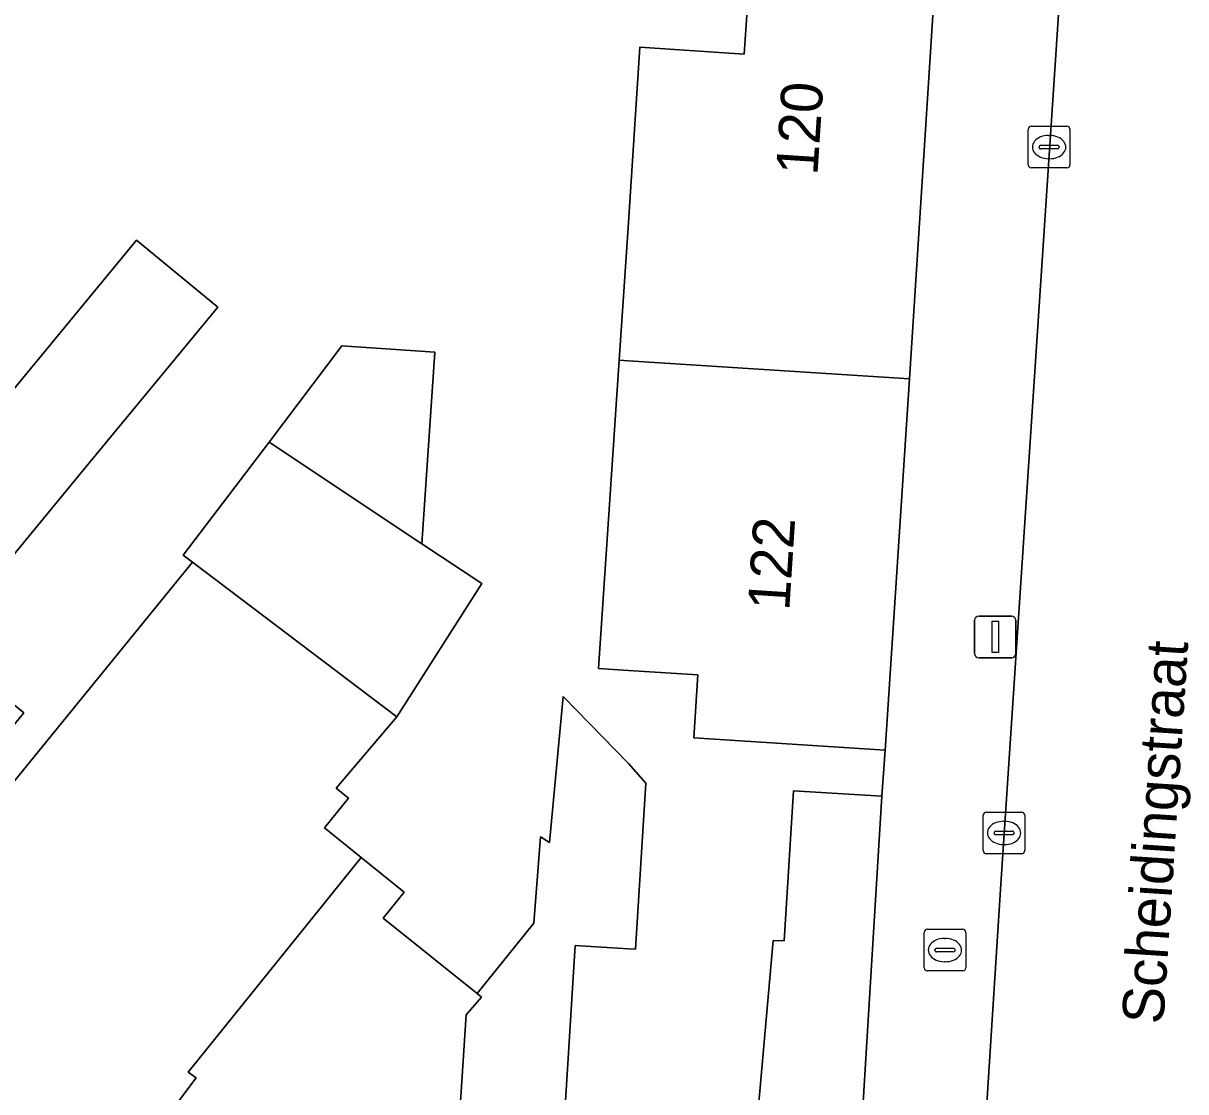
# Model space of a CAD drawing. Extents: x 160157 to 160921, y 381516 to 382045.
# Drawn here: x 160485.46 to 160513.39, y 381831.28 to 381856.97 of the extents above; entities that cross this region are included whole.
import ezdxf

# ---------------------------------------------------------------- set-up
doc = ezdxf.new("R2010")
doc.units = 0
for name, color, linetype in [('IMGEO_Brandkraan', 7, 'Continuous'), ('IMGEO_Erf', 7, 'Continuous'), ('IMGEO_Kolk', 7, 'Continuous'), ('IMGEO_Lichtmast', 7, 'Continuous'), ('IMGEO_Openbare_ruimte_label', 7, 'Continuous'), ('IMGEO_Pand', 7, 'Continuous'), ('IMGEO_Pand_nummerreeks', 7, 'Continuous'), ('IMGEO_Rijbaan_lokaal_open', 7, 'Continuous'), ('IMGEO_Voetpad_open', 7, 'Continuous')]:
    doc.layers.add(name, color=color, linetype=linetype)

msp = doc.modelspace()

# ---------------------------------------------------------------- linework, layer by layer
at = {"layer": 'IMGEO_Brandkraan'}
for p, q in [((160507.106, 381834.263), (160507.106, 381835.115)), ((160507.181, 381835.189), (160508.033, 381835.189)), ((160507.594, 381834.969), (160507.619, 381834.969)), ((160508.107, 381835.115), (160508.107, 381834.263)), ((160507.365, 381834.683), (160507.365, 381834.695)), ((160507.408, 381834.732), (160507.806, 381834.732)), ((160507.849, 381834.695), (160507.849, 381834.683)), ((160507.803, 381834.646), (160507.405, 381834.646)), ((160507.617, 381834.409), (160507.592, 381834.409)), ((160508.033, 381834.189), (160507.181, 381834.189))]:
    msp.add_line(p, q, dxfattribs=at)
for points in [[(160507.106, 381834.263), (160507.106, 381835.115)], [(160507.181, 381835.189), (160508.033, 381835.189)], [(160508.107, 381835.115), (160508.107, 381834.263)], [(160508.033, 381834.189), (160507.181, 381834.189)]]:
    msp.add_lwpolyline(points, dxfattribs=at)
for centre, radius, start, end in [((160507.183, 381835.113), 0.0765, 91.552, 178.448), ((160507.183, 381835.113), 0.0765, 91.552, 178.448), ((160508.031, 381835.113), 0.0765, 1.552, 88.448), ((160508.031, 381835.113), 0.0765, 1.552, 88.448), ((160507.405, 381834.692), 0.0403, 85.8775, 175.7526), ((160507.81, 381834.694), 0.0386, 1.7309, 96.639), ((160507.402, 381834.682), 0.0366, 178.938, 274.7102), ((160507.806, 381834.689), 0.043, 264.8664, 352.4533), ((160507.183, 381834.265), 0.0765, 181.552, 268.448), ((160507.183, 381834.265), 0.0765, 181.552, 268.448), ((160508.031, 381834.265), 0.0765, 271.552, 358.448), ((160508.031, 381834.265), 0.0765, 271.552, 358.448)]:
    msp.add_arc(centre, radius, start, end, dxfattribs=at)
for centre, major_axis, ratio, start_param, end_param in [((160507.593, 381834.689), (-0.387, 0.002), 0.722429, 4.712389, 7.853982), ((160507.618, 381834.689), (-0.39, 0.002), 0.717154, 1.570796, 4.712389)]:
    msp.add_ellipse(centre, major_axis=major_axis, ratio=ratio, start_param=start_param, end_param=end_param, dxfattribs=at)
at = {"layer": 'IMGEO_Erf'}
for points in [[(160503.001, 381829.486), (160503.479, 381834.92), (160503.742, 381834.909), (160503.965, 381838.518), (160506.091, 381838.386), (160506.173, 381839.496), (160501.57, 381839.794), (160501.668, 381841.304), (160500.001, 381841.412), (160499.283, 381841.461), (160499.779, 381848.873), (160500, 381852.181), (160500.273, 381856.394), (160502.782, 381856.231), (160502.874, 381857.649)], [(160484.957, 381847.845), (160488.178, 381851.756), (160490.129, 381850.149), (160486.907, 381846.238), (160483.459, 381842.052), (160485.473, 381840.393), (160483.484, 381837.978)], [(160483.249, 381836.314), (160489.523, 381844.017), (160489.303, 381844.183), (160491.363, 381846.903), (160493.113, 381849.214), (160495.348, 381849.064), (160495.039, 381844.456), (160496.477, 381843.499), (160494.435, 381840.297), (160492.975, 381838.584), (160493.273, 381838.344), (160492.694, 381837.625), (160493.577, 381836.913), (160494.608, 381836.082), (160494.108, 381835.46), (160496.361, 381833.644), (160497.725, 381835.337), (160497.884, 381837.409), (160498.102, 381837.278), (160498.428, 381840.783), (160500, 381839.172), (160500.415, 381838.702), (160500.169, 381834.713), (160500, 381834.723), (160498.719, 381834.802), (160498.409, 381829.769)]]:
    msp.add_lwpolyline(points, dxfattribs=at)
at = {"layer": 'IMGEO_Kolk'}
for p, q in [((160509.609, 381853.568), (160509.609, 381854.42)), ((160509.684, 381854.494), (160510.536, 381854.494)), ((160510.097, 381854.274), (160510.122, 381854.274)), ((160510.61, 381854.42), (160510.61, 381853.568)), ((160509.868, 381853.988), (160509.868, 381854)), ((160509.911, 381854.037), (160510.309, 381854.037)), ((160510.352, 381854), (160510.352, 381853.988)), ((160510.306, 381853.951), (160509.908, 381853.951)), ((160510.12, 381853.714), (160510.095, 381853.714)), ((160510.536, 381853.494), (160509.684, 381853.494)), ((160508.527, 381837.08), (160508.527, 381837.932)), ((160508.602, 381838.006), (160509.454, 381838.006)), ((160509.015, 381837.786), (160509.04, 381837.786)), ((160509.528, 381837.932), (160509.528, 381837.08)), ((160508.786, 381837.5), (160508.786, 381837.512)), ((160508.829, 381837.549), (160509.227, 381837.549)), ((160509.27, 381837.512), (160509.27, 381837.5)), ((160509.224, 381837.463), (160508.826, 381837.463)), ((160509.038, 381837.226), (160509.013, 381837.226)), ((160509.454, 381837.006), (160508.602, 381837.006))]:
    msp.add_line(p, q, dxfattribs=at)
for points in [[(160509.609, 381853.568), (160509.609, 381854.42)], [(160509.684, 381854.494), (160510.536, 381854.494)], [(160510.61, 381854.42), (160510.61, 381853.568)], [(160510.536, 381853.494), (160509.684, 381853.494)], [(160508.527, 381837.08), (160508.527, 381837.932)], [(160508.602, 381838.006), (160509.454, 381838.006)], [(160509.528, 381837.932), (160509.528, 381837.08)], [(160509.454, 381837.006), (160508.602, 381837.006)]]:
    msp.add_lwpolyline(points, dxfattribs=at)
for centre, radius, start, end in [((160509.686, 381854.418), 0.0765, 91.552, 178.448), ((160509.686, 381854.418), 0.0765, 91.552, 178.448), ((160510.534, 381854.418), 0.0765, 1.552, 88.448), ((160510.534, 381854.418), 0.0765, 1.552, 88.448), ((160509.908, 381853.997), 0.0403, 85.8775, 175.7526), ((160509.905, 381853.987), 0.0366, 178.938, 274.7102), ((160510.309, 381853.994), 0.043, 264.8664, 352.4533), ((160510.313, 381853.999), 0.0386, 1.7309, 96.639), ((160509.686, 381853.57), 0.0765, 181.552, 268.448), ((160509.686, 381853.57), 0.0765, 181.552, 268.448), ((160510.534, 381853.57), 0.0765, 271.552, 358.448), ((160510.534, 381853.57), 0.0765, 271.552, 358.448), ((160508.604, 381837.93), 0.0765, 91.552, 178.448), ((160508.604, 381837.93), 0.0765, 91.552, 178.448), ((160509.452, 381837.93), 0.0765, 1.552, 88.448), ((160509.452, 381837.93), 0.0765, 1.552, 88.448), ((160508.826, 381837.509), 0.0403, 85.8775, 175.7526), ((160508.823, 381837.499), 0.0366, 178.938, 274.7102), ((160509.227, 381837.506), 0.043, 264.8664, 352.4533), ((160509.231, 381837.511), 0.0386, 1.7309, 96.639), ((160508.604, 381837.082), 0.0765, 181.552, 268.448), ((160508.604, 381837.082), 0.0765, 181.552, 268.448), ((160509.452, 381837.082), 0.0765, 271.552, 358.448), ((160509.452, 381837.082), 0.0765, 271.552, 358.448)]:
    msp.add_arc(centre, radius, start, end, dxfattribs=at)
for centre, major_axis, ratio, start_param, end_param in [((160510.096, 381853.994), (-0.387, 0.002), 0.722429, 4.712389, 7.853982), ((160510.121, 381853.994), (-0.39, 0.002), 0.717154, 1.570796, 4.712389), ((160509.014, 381837.506), (-0.387, 0.002), 0.722429, 4.712389, 7.853982), ((160509.039, 381837.506), (-0.39, 0.002), 0.717154, 1.570796, 4.712389)]:
    msp.add_ellipse(centre, major_axis=major_axis, ratio=ratio, start_param=start_param, end_param=end_param, dxfattribs=at)
at = {"layer": 'IMGEO_Lichtmast'}
for p, q in [((160508.32, 381841.818), (160508.32, 381842.618)), ((160508.32, 381842.618), (160508.32, 381841.818)), ((160508.42, 381842.718), (160509.21, 381842.718)), ((160509.21, 381842.718), (160508.42, 381842.718)), ((160509.31, 381842.618), (160509.31, 381841.818)), ((160509.31, 381841.818), (160509.31, 381842.618)), ((160509.21, 381841.718), (160508.42, 381841.718)), ((160508.42, 381841.718), (160509.21, 381841.718))]:
    msp.add_line(p, q, dxfattribs=at)
msp.add_lwpolyline([(160508.74, 381842.593), (160508.89, 381842.593), (160508.89, 381841.843), (160508.74, 381841.843), (160508.74, 381842.593)], dxfattribs=at)
for centre, start, end in [((160508.42, 381842.618), 90, 180), ((160508.42, 381842.618), 90, 180), ((160509.21, 381842.618), 0, 90), ((160509.21, 381842.618), 360, 90), ((160508.42, 381841.818), 180, 270), ((160508.42, 381841.818), 180, 270), ((160509.21, 381841.818), 270, 0), ((160509.21, 381841.818), 270, 0)]:
    msp.add_arc(centre, 0.1, start, end, dxfattribs=at)
at = {"layer": 'IMGEO_Pand'}
for points in [[(160506.751, 381848.424), (160507.527, 381860.411), (160502.175, 381861.609), (160500.129, 381858.808), (160502.874, 381857.649), (160502.782, 381856.231), (160500.273, 381856.394), (160500, 381852.181), (160499.779, 381848.873), (160500, 381848.859)], [(160483.459, 381842.052), (160486.907, 381846.238), (160490.129, 381850.149), (160488.178, 381851.756), (160484.957, 381847.845), (160476.341, 381837.384), (160480.304, 381834.119), (160483.484, 381837.978), (160485.473, 381840.393)], [(160491.363, 381846.903), (160495.039, 381844.456), (160495.348, 381849.064), (160493.113, 381849.214)], [(160506.751, 381848.424), (160500, 381848.859), (160499.779, 381848.873), (160499.283, 381841.461), (160500.001, 381841.412), (160501.668, 381841.304), (160501.57, 381839.794), (160506.173, 381839.496)], [(160495.039, 381844.456), (160491.363, 381846.903), (160489.303, 381844.183), (160489.523, 381844.017), (160494.435, 381840.297), (160496.477, 381843.499)], [(160489.609, 381831.618), (160489.422, 381831.756), (160493.577, 381836.913), (160492.694, 381837.625), (160493.273, 381838.344), (160492.975, 381838.584), (160494.435, 381840.297), (160489.523, 381844.017), (160483.249, 381836.314), (160481.128, 381833.441), (160478.504, 381829.886), (160484.936, 381825.138), (160487.416, 381828.497), (160487.323, 381828.564)], [(160495.382, 381822.078), (160499.999, 381821.794), (160500.249, 381821.779), (160500.868, 381829.617), (160500, 381829.671), (160498.409, 381829.769), (160498.719, 381834.802), (160500, 381834.723), (160500.169, 381834.713), (160500.415, 381838.702), (160500, 381839.172), (160498.428, 381840.783), (160498.102, 381837.278), (160497.884, 381837.409), (160497.725, 381835.337), (160496.361, 381833.644), (160496.469, 381833.557), (160496.097, 381833.132)], [(160505.533, 381829.33), (160506.091, 381838.386), (160503.965, 381838.518), (160503.742, 381834.909), (160503.479, 381834.92), (160503.001, 381829.486), (160500.868, 381829.617), (160500.249, 381821.779), (160505.049, 381821.483)], [(160489.422, 381831.756), (160489.609, 381831.618), (160487.323, 381828.564), (160487.416, 381828.497), (160495.382, 381822.078), (160496.097, 381833.132), (160496.469, 381833.557), (160496.361, 381833.644), (160494.108, 381835.46), (160494.608, 381836.082), (160493.577, 381836.913)]]:
    msp.add_lwpolyline(points, close=True, dxfattribs=at)
at = {"layer": 'IMGEO_Rijbaan_lokaal_open'}
msp.add_lwpolyline([(160511.622, 381876.467), (160510.794, 381864.027), (160510.338, 381857.185), (160508.946, 381836.272), (160507.968, 381820.837), (160510.711, 381820.693), (160513.972, 381820.522), (160515.631, 381846.447), (160517.644, 381875.952)], dxfattribs=at)
at = {"layer": 'IMGEO_Voetpad_open'}
for points in [[(160518.133, 381941.164), (160512.953, 381943.6), (160512.664, 381937.5), (160512.303, 381931.376), (160511.943, 381925.27), (160511.802, 381923.23), (160513.235, 381923.143), (160512.824, 381916.285), (160512.401, 381909.234), (160511.844, 381899.716), (160511.254, 381891.713), (160509.584, 381891.836), (160509.474, 381890.439), (160509.028, 381883.948), (160508.982, 381882.876), (160508.58, 381876.669), (160508.261, 381871.744), (160507.527, 381860.411), (160506.751, 381848.424), (160506.173, 381839.496), (160506.091, 381838.386), (160505.533, 381829.33), (160505.049, 381821.483), (160501.303, 381815.777)], [(160507.908, 381819.84), (160507.968, 381820.837), (160508.946, 381836.272), (160510.338, 381857.185), (160510.794, 381864.027)]]:
    msp.add_lwpolyline(points, dxfattribs=at)

# ---------------------------------------------------------------- texts
at = {"layer": 'IMGEO_Openbare_ruimte_label'}
msp.add_text('Scheidingstraat', height=1, rotation=86.2736, dxfattribs=at).set_placement((160512.853, 381832.891))
at = {"layer": 'IMGEO_Pand_nummerreeks'}
for s, rotation, p in [('120', 86.296, (160504.541, 381853.3)), ('122', 86.2958, (160503.864, 381842.836))]:
    msp.add_text(s, height=1, rotation=rotation, dxfattribs=at).set_placement(p)

doc.saveas('drawing.dxf')
